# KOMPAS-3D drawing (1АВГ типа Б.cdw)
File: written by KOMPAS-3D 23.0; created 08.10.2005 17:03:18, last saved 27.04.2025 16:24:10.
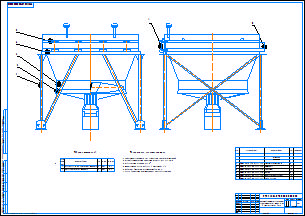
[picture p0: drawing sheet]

Sheet 1: A1, landscape

Document properties: Полное имя файла: G:\Учёба\Курсовое проектирование\ПиА курсовой проект\АВО Дамир Бакеев\Для публикации\1АВГ типа Б.cdw

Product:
- Part/product: (unnamed)  | designation УТЭК.18.02.09.ПП.00.00.000.ВО

Title block, sheet 1: Наименование: Аппарат воздушного охлаждения / горизонтального типа 1АВГ / Чертеж общего вида; designation: УТЭК.18.02.09.ПП.00.00.000.ВО; scale: 1:20; Количество листов документа: 1; Форматы листов документа: A1; stored path: C:\Documents and Settings\Администратор\Мои документы\Курсовой проект\Чертеж.cdw

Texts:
  Normal
  Слой 1
  Поз.
  Кол.
  УТЭК 18.02.09 ПП.00.00.001
  Металлоконструкция
  Детали
  УТЭК 18.02.09 ПП.00.00.002
  Диффузор
  УТЭК 18.02.09 ПП.00.00.003
  Коллектор
  УТЭК 18.02.09 ПП.00.00.004
  Жалюзи
  УТЭК 18.02.09 ПП.00.00.005
  Теплообменная секция
  УТЭК 18.02.09 ПП.00.00.006
  Рамка сборная
  Техническая характеристика
  Аппарат предназначен для охлаждения дизельного топлива
  Производительность аппарата по сырью 200 000 кг/ч
  Поверхность секции 4760 м 2
  Температура среды на входе в аппарат 260␣С
  Symbol
  Давление в трубном пространстве 4 МПа
  Среда в аппарате малотоксичная, слабокоррозионная
  Таблица штуцеров
  Обоз-
  наче-
  ние
  Dу, мм
  Pу, МПа
  Ввод паров смеси дизельного топлива
  Вывод дизельного топлива
Dimensions and other numbers on the sheet: 1; 4; 2; 3; 5; 6; 250; 4,0; 1:20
